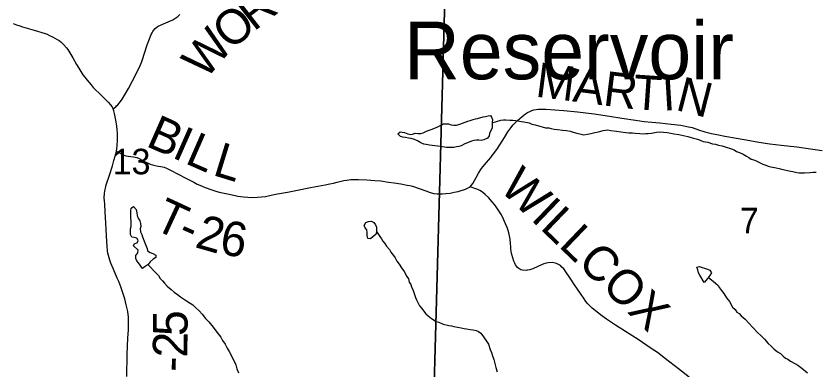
# Model space of a CAD drawing. Extents: x -7.9 to 76.1, y 0 to 22.
# Drawn here: x 2.706 to 4.02, y 18.425 to 19.006 of the extents above; entities that cross this region are included whole.
import ezdxf

# ---------------------------------------------------------------- set-up
doc = ezdxf.new("R2010")
doc.units = 0
for name, color, linetype in [('GM_X_Minor_Lake_Text', 7, 'Continuous'), ('GM_X_Minor_River', 7, 'Continuous'), ('GM_X_Section', 7, 'Continuous'), ('GM_X_Section_Text', 7, 'Continuous'), ('GM_X_Township_Road', 7, 'Continuous'), ('GM_X_Township_Road_Text', 7, 'Continuous')]:
    doc.layers.add(name, color=color, linetype=linetype)

msp = doc.modelspace()

# ---------------------------------------------------------------- linework, layer by layer
at = {"layer": 'GM_X_Minor_River'}
for points in [[(3.4869, 18.8398), (3.4884, 18.8361), (3.4881, 18.8312), (3.4881, 18.8274), (3.4879, 18.8217), (3.486, 18.8179), (3.4835, 18.8129), (3.4828, 18.8091), (3.4802, 18.8053), (3.4742, 18.8025), (3.4697, 18.8017), (3.4659, 18.802), (3.4621, 18.8019), (3.4576, 18.8015), (3.4538, 18.8006), (3.45, 18.799), (3.4433, 18.7963), (3.4373, 18.7931), (3.4331, 18.7919), (3.4294, 18.7911), (3.4248, 18.7902), (3.4127, 18.79), (3.4032, 18.7918), (3.3892, 18.7934), (3.3851, 18.7937), (3.3797, 18.7948), (3.3759, 18.7954), (3.3706, 18.7976), (3.3653, 18.8009), (3.3603, 18.8031), (3.355, 18.8049), (3.3504, 18.8056), (3.3455, 18.8063), (3.3413, 18.807), (3.3375, 18.8084), (3.3329, 18.8125), (3.3366, 18.8156), (3.3404, 18.8153), (3.3442, 18.8146), (3.3495, 18.8124), (3.3533, 18.8117), (3.3571, 18.8122), (3.3616, 18.8134), (3.3658, 18.8131), (3.3707, 18.8132), (3.3745, 18.814), (3.3801, 18.8171), (3.3846, 18.8187), (3.3895, 18.8203), (3.3959, 18.8231), (3.4, 18.8247), (3.4038, 18.8267), (3.4079, 18.829), (3.4117, 18.8291), (3.4162, 18.8288), (3.4208, 18.8273), (3.425, 18.8267), (3.4295, 18.8267), (3.4348, 18.8287), (3.4434, 18.8315), (3.4479, 18.8335), (3.4521, 18.8343), (3.4566, 18.8359), (3.4604, 18.8371), (3.4641, 18.838), (3.4732, 18.8404), (3.4769, 18.8412), (3.4815, 18.8421), (3.4852, 18.8425), (3.4869, 18.8398)], [(3.4881, 18.8304), (3.5024, 18.8352), (3.5066, 18.8353), (3.5103, 18.8358), (3.5171, 18.8351), (3.5217, 18.8348), (3.527, 18.8342), (3.5361, 18.8328), (3.5399, 18.8321), (3.5486, 18.8304), (3.5532, 18.8286), (3.5585, 18.8275), (3.5627, 18.8261), (3.5703, 18.8243), (3.5756, 18.8225), (3.5809, 18.8222), (3.5851, 18.8212), (3.5901, 18.8201), (3.5954, 18.8194), (3.6037, 18.8188), (3.6102, 18.8178), (3.6162, 18.8168), (3.6212, 18.8154), (3.6269, 18.8136), (3.6341, 18.8118), (3.6387, 18.8107), (3.6447, 18.812), (3.6503, 18.8132), (3.6567, 18.8148), (3.6624, 18.8161), (3.6703, 18.8181), (3.6779, 18.819), (3.6828, 18.8183), (3.6923, 18.817), (3.6995, 18.8156), (3.7075, 18.815), (3.7124, 18.8143), (3.7184, 18.814), (3.723, 18.8137), (3.7306, 18.8131), (3.7359, 18.8125), (3.7404, 18.8129), (3.7442, 18.813), (3.7495, 18.8135), (3.7578, 18.8151), (3.7638, 18.8156), (3.7695, 18.8153), (3.7756, 18.8147), (3.7816, 18.8136), (3.7866, 18.8126), (3.7945, 18.8112), (3.8094, 18.8081), (3.8147, 18.8063), (3.8185, 18.8052), (3.8253, 18.8038), (3.8295, 18.802), (3.8348, 18.8002), (3.8424, 18.7988), (3.8501, 18.7963), (3.855, 18.7956), (3.8599, 18.7938), (3.866, 18.7928), (3.871, 18.791), (3.8812, 18.7881), (3.8854, 18.7863), (3.8896, 18.7837), (3.8942, 18.7819), (3.9003, 18.779), (3.906, 18.7757), (3.9098, 18.7738), (3.9137, 18.7709), (3.9194, 18.7691), (3.9282, 18.7647), (3.9327, 18.7625), (3.9377, 18.761), (3.9415, 18.7596), (3.9457, 18.7585), (3.9548, 18.7568), (3.9594, 18.7554), (3.9635, 18.7547), (3.9708, 18.7529), (3.978, 18.7515), (3.9821, 18.7505), (3.9886, 18.7491), (3.9924, 18.7487), (3.9969, 18.7484), (4.0011, 18.7485), (4.0102, 18.7491), (4.0151, 18.7495), (4.02, 18.7496)], [(2.9136, 18.5911), (2.9071, 18.6005), (2.904, 18.6042), (2.9024, 18.608), (2.9027, 18.6125), (2.9057, 18.6171), (2.9067, 18.6217), (2.8987, 18.6288), (2.9005, 18.6326), (2.905, 18.6334), (2.9065, 18.6373), (2.9045, 18.641), (2.8999, 18.6421), (2.8958, 18.6428), (2.8938, 18.6473), (2.8937, 18.6514), (2.894, 18.6564), (2.8947, 18.6606), (2.895, 18.6655), (2.8949, 18.6701), (2.8945, 18.6738), (2.8943, 18.6863), (2.8949, 18.6902), (2.8987, 18.6933), (2.9029, 18.6884), (2.9042, 18.6827), (2.905, 18.6786), (2.9066, 18.6741), (2.9093, 18.6699), (2.9105, 18.665), (2.9106, 18.6605), (2.9099, 18.6563), (2.9104, 18.6517), (2.9123, 18.6472), (2.9136, 18.6431), (2.9175, 18.6337), (2.9195, 18.628), (2.9211, 18.6243), (2.9219, 18.6205), (2.9261, 18.6175), (2.9307, 18.6161), (2.9353, 18.6135), (2.9353, 18.6097), (2.9312, 18.6066), (2.9264, 18.6024), (2.9227, 18.5981), (2.9182, 18.5946), (2.9136, 18.5911)], [(3.284, 18.6406), (3.2824, 18.6455), (3.2827, 18.6504), (3.2823, 18.6546), (3.2792, 18.6583), (3.2776, 18.6621), (3.2802, 18.6667), (3.2847, 18.6683), (3.2896, 18.6691), (3.2934, 18.6669), (3.2961, 18.6632), (3.2977, 18.6594), (3.2982, 18.6549), (3.2982, 18.6511), (3.2968, 18.6473), (3.2927, 18.6438), (3.2882, 18.6403), (3.284, 18.6406)], [(3.2982, 18.6521), (3.3037, 18.644), (3.3064, 18.6402), (3.3083, 18.6365), (3.3114, 18.6324), (3.3145, 18.6279), (3.3192, 18.6223), (3.3215, 18.6181), (3.3261, 18.6129), (3.3289, 18.6088), (3.3316, 18.6035), (3.3351, 18.5983), (3.339, 18.5927), (3.3433, 18.5863), (3.3476, 18.5784), (3.3503, 18.5743), (3.3515, 18.569), (3.3542, 18.5649), (3.3554, 18.5611), (3.3582, 18.5551), (3.3598, 18.5502), (3.3622, 18.5438), (3.3637, 18.54), (3.3688, 18.5302), (3.3727, 18.5254), (3.3754, 18.5216), (3.3789, 18.5171), (3.3831, 18.5138), (3.3885, 18.5093), (3.3958, 18.5045), (3.4003, 18.5031), (3.4076, 18.4998), (3.4167, 18.4977), (3.4212, 18.497), (3.425, 18.4963), (3.4311, 18.4949), (3.4368, 18.4939), (3.4421, 18.4928), (3.4459, 18.4922), (3.452, 18.4911), (3.4565, 18.4905), (3.4619, 18.4894), (3.4657, 18.488), (3.4695, 18.4854), (3.4738, 18.479), (3.4788, 18.4719), (3.4819, 18.467), (3.4847, 18.4583), (3.4871, 18.4534), (3.4887, 18.4478), (3.4907, 18.4421), (3.4931, 18.4331), (3.4939, 18.4289), (3.496, 18.4214)], [(2.9223, 18.5978), (2.9358, 18.5836), (2.9396, 18.5798), (2.9427, 18.575), (2.9466, 18.5712), (2.9497, 18.5675), (2.9543, 18.5626), (2.9608, 18.5567), (2.9658, 18.5526), (2.9712, 18.5485), (2.9762, 18.5448), (2.9808, 18.5415), (2.9858, 18.5382), (2.9919, 18.5345), (2.9961, 18.5315), (3.0007, 18.5271), (3.0065, 18.5219), (3.0115, 18.5163), (3.0169, 18.5095), (3.0227, 18.5039), (3.0277, 18.498), (3.0378, 18.4841), (3.042, 18.4785), (3.0452, 18.4729), (3.0491, 18.4669), (3.0526, 18.4605), (3.0561, 18.4549), (3.0592, 18.4492), (3.062, 18.4432), (3.0655, 18.4372), (3.0667, 18.4334), (3.0687, 18.4266), (3.0711, 18.4202)], [(3.8362, 18.5684), (3.8292, 18.5805), (3.8272, 18.5843), (3.8257, 18.5892), (3.8244, 18.5933), (3.8286, 18.5949), (3.8332, 18.5931), (3.837, 18.592), (3.8415, 18.5902), (3.8457, 18.5888), (3.8484, 18.5843), (3.8455, 18.5797), (3.8425, 18.5754), (3.8362, 18.5684)], [(3.8434, 18.5766), (3.8509, 18.5707), (3.8556, 18.5669), (3.859, 18.5632), (3.8617, 18.5595), (3.8648, 18.555), (3.8687, 18.5501), (3.873, 18.5434), (3.8776, 18.537), (3.8827, 18.528), (3.887, 18.5239), (3.8897, 18.5198), (3.8935, 18.5176), (3.8973, 18.5138), (3.9035, 18.5079), (3.9097, 18.5015), (3.9239, 18.4862), (3.9297, 18.4807), (3.9351, 18.4751), (3.9416, 18.4683), (3.9463, 18.4639), (3.9505, 18.4594), (3.9566, 18.4546), (3.9616, 18.4516), (3.9659, 18.4475), (3.9701, 18.4442), (3.9739, 18.4427), (3.9781, 18.4394), (3.985, 18.4354), (3.9903, 18.4328), (3.9945, 18.4295), (3.9992, 18.4257), (4.0061, 18.4198)]]:
    msp.add_lwpolyline(points, dxfattribs=at)
at = {"layer": 'GM_X_Section'}
for points in [[(3.4168, 19.2711), (3.389, 18.2623), (2.381, 18.2821), (2.4057, 19.2962)], [(3.4168, 19.2711), (4.4336, 19.2503), (4.4107, 18.2442), (3.389, 18.2623)]]:
    msp.add_lwpolyline(points, close=True, dxfattribs=at)
at = {"layer": 'GM_X_Township_Road'}
for points in [[(2.8652, 18.8536), (2.8695, 18.8571), (2.8711, 18.8585), (2.8732, 18.8604), (2.8753, 18.8627), (2.8775, 18.8656), (2.8803, 18.8696), (2.8849, 18.8775), (2.8904, 18.8869), (2.8971, 18.8995), (2.9038, 18.9123), (2.9099, 18.9246), (2.9115, 18.9285), (2.913, 18.9328), (2.9214, 18.9586), (2.9249, 18.9685), (2.928, 18.9758), (2.9293, 18.9784), (2.9308, 18.9809), (2.9317, 18.9823), (2.9343, 18.9854), (2.9377, 18.9881), (2.9395, 18.9893), (2.9558, 18.9964), (2.9633, 18.9999), (2.9665, 19.0018), (2.9685, 19.0032), (2.9715, 19.0055), (2.975, 19.0086)], [(2.701, 18.9938), (2.7064, 18.9918), (2.7119, 18.9899), (2.7167, 18.9884), (2.7354, 18.9827), (2.7537, 18.9771), (2.7568, 18.976), (2.7609, 18.9743), (2.7659, 18.972), (2.7736, 18.9677), (2.7768, 18.9656), (2.7796, 18.9634), (2.7846, 18.9589), (2.7889, 18.9537), (2.7908, 18.9509), (2.7991, 18.9373), (2.8051, 18.9267), (2.8088, 18.9205), (2.8158, 18.9097), (2.8187, 18.9056), (2.8224, 18.9008), (2.8291, 18.8929), (2.8327, 18.8889), (2.8462, 18.8757), (2.8574, 18.8647), (2.8612, 18.8602), (2.8634, 18.8572), (2.8652, 18.8536)], [(2.8706, 18.7841), (2.8712, 18.7879), (2.8719, 18.7934), (2.8726, 18.8024), (2.8723, 18.8143), (2.872, 18.8184), (2.8712, 18.8257), (2.8696, 18.8351), (2.8674, 18.8462), (2.8663, 18.8504), (2.8652, 18.8536)], [(2.8706, 18.7841), (2.8795, 18.7793), (2.882, 18.7781), (2.8844, 18.7772), (2.887, 18.7764), (2.89, 18.776), (2.8986, 18.7748), (2.9015, 18.7743), (2.9041, 18.7736), (2.908, 18.7721), (2.9141, 18.7687), (2.9182, 18.7666), (2.9228, 18.7643), (2.9262, 18.7629), (2.9302, 18.7616), (2.9343, 18.7606), (2.9394, 18.7596), (2.9438, 18.7588), (2.9462, 18.7584), (2.949, 18.7577), (2.9541, 18.7557), (2.9596, 18.7531), (2.972, 18.7465), (2.9846, 18.7399), (2.9977, 18.733), (3.0034, 18.7301), (3.0075, 18.7282), (3.0166, 18.7244), (3.0276, 18.7204), (3.0339, 18.7184), (3.0395, 18.7169), (3.0531, 18.7139), (3.0656, 18.711), (3.0704, 18.7101), (3.0745, 18.7094), (3.0795, 18.7089), (3.0866, 18.7084), (3.0948, 18.7082), (3.1024, 18.7083), (3.1092, 18.7088), (3.1158, 18.7097), (3.127, 18.7121), (3.1352, 18.7139), (3.1515, 18.717), (3.1653, 18.7197), (3.1898, 18.7243), (3.2139, 18.7289), (3.2213, 18.7303), (3.2273, 18.7317), (3.2335, 18.7333), (3.2401, 18.735), (3.2444, 18.7359), (3.2491, 18.7366), (3.2556, 18.7373), (3.2615, 18.7376), (3.2683, 18.7375), (3.282, 18.737), (3.2952, 18.7361), (3.305, 18.7351), (3.3177, 18.7333), (3.327, 18.732), (3.3378, 18.7304), (3.3481, 18.7285), (3.3528, 18.7275), (3.3572, 18.7264), (3.379, 18.719), (3.386, 18.7164), (3.3923, 18.7148), (3.3976, 18.7139), (3.4012, 18.7138), (3.4065, 18.7139), (3.4119, 18.7143), (3.4192, 18.7153), (3.4257, 18.7165), (3.432, 18.718), (3.4443, 18.7218), (3.4465, 18.7226), (3.4484, 18.7236), (3.4518, 18.7256), (3.4541, 18.7282), (3.4561, 18.7312), (3.4616, 18.7411), (3.4653, 18.7477), (3.4706, 18.7555), (3.4753, 18.7618), (3.4858, 18.7738), (3.4882, 18.7768), (3.4925, 18.7824), (3.4967, 18.7884), (3.5082, 18.8068), (3.5139, 18.8156), (3.5188, 18.8225), (3.5224, 18.8271), (3.5244, 18.8294), (3.5295, 18.8344), (3.5334, 18.8379), (3.5372, 18.841), (3.543, 18.8453), (3.5462, 18.8475), (3.5498, 18.8494), (3.5533, 18.8508), (3.5565, 18.8517), (3.56, 18.8524), (3.5635, 18.8528), (3.5674, 18.853), (3.5763, 18.8528), (3.5909, 18.8519), (3.6059, 18.8511), (3.628, 18.8488), (3.6553, 18.8453), (3.6807, 18.8414), (3.7012, 18.8383), (3.7233, 18.8349), (3.7376, 18.833), (3.7501, 18.8315), (3.7635, 18.8304), (3.782, 18.8286), (3.7977, 18.8266), (3.8079, 18.8248), (3.8164, 18.8227), (3.8272, 18.8193), (3.8376, 18.8161), (3.8484, 18.8133), (3.8597, 18.8108), (3.8704, 18.8088), (3.8894, 18.8055), (3.9112, 18.8017), (3.9262, 18.7991), (3.9439, 18.7963), (3.963, 18.794), (3.9885, 18.791), (4.0107, 18.7881), (4.0303, 18.7854)], [(2.888, 18.4137), (2.8882, 18.4501), (2.8888, 18.464), (2.8895, 18.4769), (2.8903, 18.4906), (2.8905, 18.4985), (2.8904, 18.5037), (2.8903, 18.5117), (2.8899, 18.5158), (2.8892, 18.5206), (2.8882, 18.525), (2.8867, 18.5317), (2.8843, 18.5418), (2.8815, 18.5516), (2.878, 18.5612), (2.8748, 18.5699), (2.8722, 18.5756), (2.8653, 18.5914), (2.8617, 18.6001), (2.8599, 18.6051), (2.8586, 18.6091), (2.8575, 18.6127), (2.8567, 18.6165), (2.8562, 18.6204), (2.8556, 18.6278), (2.8545, 18.6444), (2.8539, 18.6562), (2.8535, 18.6656), (2.8525, 18.6842), (2.8516, 18.6968), (2.8511, 18.7026), (2.8508, 18.7077), (2.8511, 18.7145), (2.8517, 18.7192), (2.8526, 18.7234), (2.854, 18.7289), (2.8591, 18.7447), (2.8641, 18.7602), (2.8667, 18.7689), (2.8687, 18.7756), (2.8697, 18.7795), (2.8706, 18.7841)], [(3.8115, 18.4131), (3.7943, 18.4265), (3.773, 18.4431), (3.7596, 18.4533), (3.7476, 18.4613), (3.7295, 18.4734), (3.7071, 18.4878), (3.6908, 18.4984), (3.6758, 18.5084), (3.6659, 18.5153), (3.6572, 18.5222), (3.6524, 18.5262), (3.6488, 18.5295), (3.6454, 18.5333), (3.6421, 18.5374), (3.6392, 18.5414), (3.6333, 18.5501), (3.6233, 18.5648), (3.6159, 18.5756), (3.609, 18.586), (3.6055, 18.5906), (3.6026, 18.5937), (3.6, 18.5961), (3.5979, 18.5975), (3.595, 18.5992), (3.5923, 18.6002), (3.5893, 18.6008), (3.5869, 18.601), (3.5799, 18.6005), (3.5768, 18.5999), (3.5731, 18.5988), (3.569, 18.5972), (3.5629, 18.5944), (3.5547, 18.591), (3.5497, 18.5893), (3.5457, 18.5885), (3.5436, 18.5882), (3.5376, 18.5885), (3.5349, 18.5894), (3.532, 18.5912), (3.5301, 18.5927), (3.5278, 18.5952), (3.5263, 18.5976), (3.525, 18.6002), (3.5237, 18.6035), (3.5218, 18.6091), (3.5203, 18.6146), (3.5194, 18.6192), (3.5187, 18.6237), (3.5184, 18.627), (3.5179, 18.6325), (3.5173, 18.6394), (3.5166, 18.6449), (3.5153, 18.65), (3.5143, 18.6537), (3.5125, 18.6588), (3.51, 18.6646), (3.5065, 18.6723), (3.5032, 18.6793), (3.5002, 18.6847), (3.4959, 18.6911), (3.492, 18.6964), (3.488, 18.7011), (3.4819, 18.7082), (3.4767, 18.7131), (3.472, 18.717), (3.4678, 18.7196), (3.4645, 18.7209), (3.4609, 18.7222), (3.4518, 18.7256)]]:
    msp.add_lwpolyline(points, dxfattribs=at)

# ---------------------------------------------------------------- texts
at = {"layer": 'GM_X_Minor_Lake_Text'}
msp.add_text('Reservoir', height=0.09469, rotation=0.0035, dxfattribs=at).set_placement((3.3434, 18.9021))
at = {"layer": 'GM_X_Section_Text'}
for s, height, p in [('13', 0.04186, (2.8644, 18.7461)), ('7', 0.0419, (3.8948, 18.6492))]:
    msp.add_text(s, height=height, rotation=0, dxfattribs=at).set_placement(p)
at = {"layer": 'GM_X_Township_Road_Text'}
for s, height, rotation, p in [('R', 0.0568, 37.8863, (3.0964, 18.9798)), ('O', 0.0568, 39.1815, (3.0579, 18.9484)), ('W', 0.0568, 49.6514, (3.0172, 18.9002)), ('M', 0.0568, 352.631, (3.5577, 18.8739)), ('A', 0.0568, 352.6287, (3.6188, 18.866)), ('R', 0.0568, 352.8975, (3.6687, 18.8595)), ('T', 0.0568, 356.0273, (3.7184, 18.8534)), ('I', 0.0568, 3.5137, (3.7689, 18.8504)), ('N', 0.0568, 345.636, (3.7875, 18.8523)), ('B', 0.0568, 336.1921, (2.9174, 18.7932)), ('I', 0.0568, 336.1905, (2.9601, 18.7744)), ('L', 0.0568, 336.3365, (2.9816, 18.7649)), ('L', 0.0568, 342.9052, (3.0271, 18.7454)), ('WILLCOX', 0.05682, 316.1651, (3.4983, 18.7217)), ('T', 0.0568, 335.1563, (2.9291, 18.6575)), ('2', 0.0568, 343.9913, (2.998, 18.6268)), ('6', 0.0568, 350.5366, (3.0385, 18.6156)), ('-', 0.0568, 336.1462, (2.9687, 18.6392)), ('5', 0.0568, 89.8436, (2.9876, 18.4804)), ('2', 0.0568, 89.1933, (2.9871, 18.4447)), ('-', 0.0568, 89.034, (2.9867, 18.4212))]:
    msp.add_text(s, height=height, rotation=rotation, dxfattribs=at).set_placement(p)

doc.saveas('drawing.dxf')
